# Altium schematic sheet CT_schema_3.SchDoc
size 235 x 258 mm
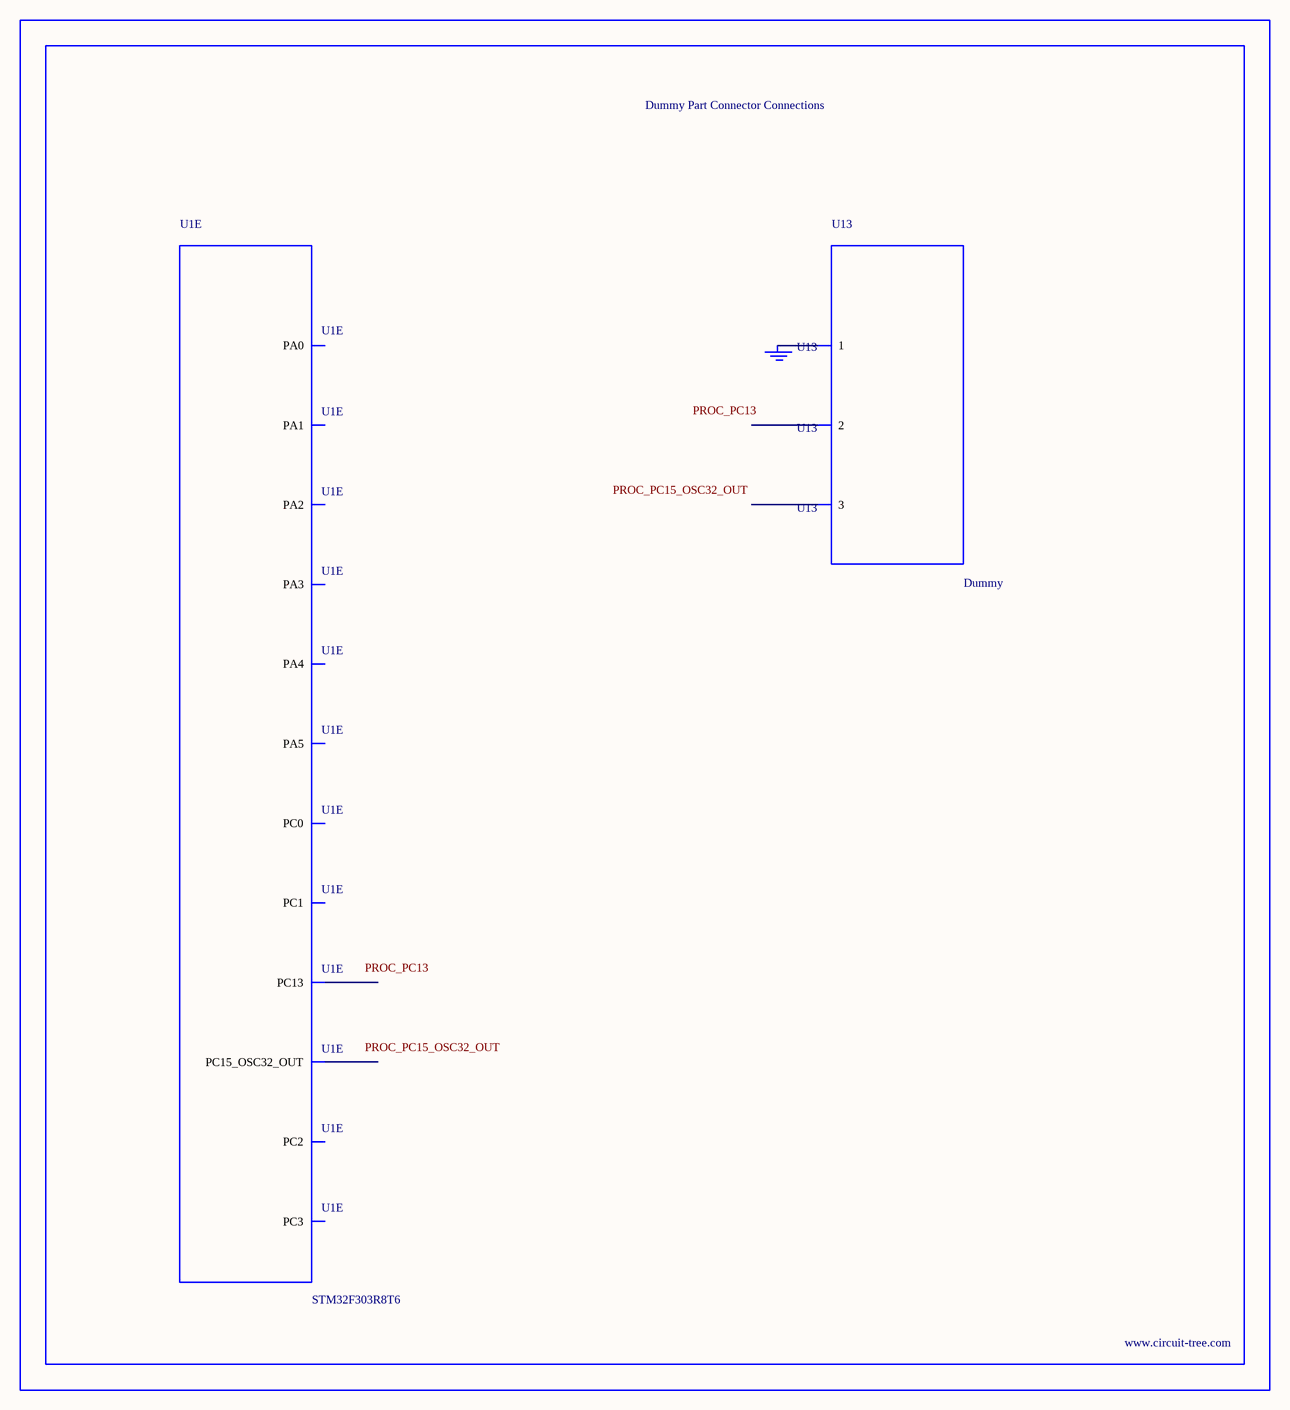
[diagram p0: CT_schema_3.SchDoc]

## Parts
BORDER2  (no value)
GND_INSTANCE_2_0  (no value)
U1  STM32F303R8T6  [LQFP64]  (part E of 5)
U13  Dummy  [DUMMY_PACKAGE_108]

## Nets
NetGND_INSTANCE_2_0_0: GND_INSTANCE_2_0.0(GND) U13.1

Not connected (* = marked no-connect by the designer): U1 2(PC13) 4(PC15_OSC32_OUT) 8(PC0) 9(PC1) 10(PC2) 11(PC3) 14(PA0) 15(PA1) 16(PA2) 17(PA3) 20(PA4) 21(PA5); U13 2 3

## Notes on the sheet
- Labels drawn without touching a wire or pin: PROC_PC13, PROC_PC15_OSC32_OUT

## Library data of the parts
BORDER2 = BORDER_PAGE2
GND_INSTANCE_2_0 = GND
